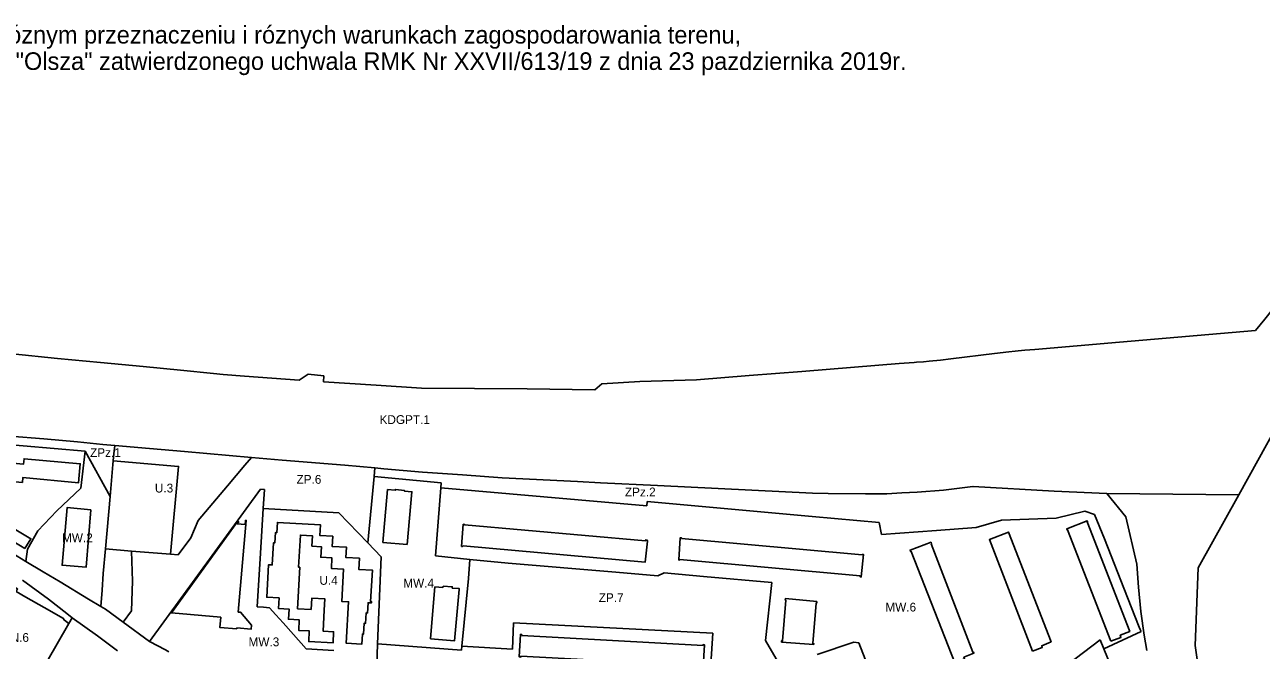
# Model space of a CAD drawing. Extents: x 7425067 to 7426806, y 5549054 to 5550619.
# Drawn here: x 7425657 to 7426359, y 5550263 to 5550619 of the extents above; entities that cross this region are included whole.
import ezdxf

# ---------------------------------------------------------------- set-up
doc = ezdxf.new("R2010")
doc.units = 0
for name, color, linetype in [('__LEGENDA_RAMKA_LOGO_PODZIAŁKA', 7, 'Continuous'), ('LIN_Linia Zabudowy Nieprzekraczalna', 7, 'Continuous'), ('LIN_linia zabudowy obowiązująca', 7, 'Continuous'), ('LIN_linie_rozgraniczajace', 7, 'Continuous'), ('TXT_Oznaczenia_przeznaczen', 7, 'Continuous')]:
    doc.layers.add(name, color=color, linetype=linetype)

msp = doc.modelspace()

# ---------------------------------------------------------------- linework, layer by layer
at = {"layer": 'LIN_Linia Zabudowy Nieprzekraczalna'}
for points in [[(7425702.5347, 5550320.8967), (7425717.29, 5550319.7), (7425739.452, 5550317.9026), (7425744.0849, 5550367.7743), (7425707.0308, 5550370.9961)], [(7425678.5251, 5550280.9263), (7425678.8, 5550281.4), (7425667.67, 5550287.68), (7425657.41, 5550293.57), (7425651.81, 5550296.72), (7425652.68, 5550298.21), (7425647.29, 5550301.26), (7425641.86, 5550304.43), (7425636.35, 5550307.4)], [(7425681.8566, 5550278.5552), (7425678.5251, 5550280.9263)]]:
    msp.add_lwpolyline(points, dxfattribs=at)
at = {"layer": 'LIN_linia zabudowy obowiązująca'}
for points in [[(7425577.83, 5550376.56), (7425576.82, 5550365.9), (7425655.37, 5550358.71), (7425655.64, 5550361.43), (7425687.2, 5550358.45), (7425688.22, 5550369.3), (7425656.31, 5550372.18), (7425656.06, 5550369.17), (7425577.83, 5550376.56)], [(7425862.71, 5550354.63), (7425860.14, 5550324.59), (7425873.91, 5550323.47), (7425876.62, 5550353.37), (7425872.39, 5550353.8), (7425872.4, 5550354.21), (7425867.21, 5550354.76), (7425867.12, 5550354.26), (7425862.71, 5550354.63)], [(7425656.83, 5550321.15), (7425660.19, 5550326.68), (7425619.2737, 5550351.0673), (7425618.47, 5550349.66), (7425616.02, 5550345.37), (7425654.29, 5550322.64), (7425656.83, 5550321.15)], [(7425694.27, 5550343.19), (7425680.89, 5550344.47), (7425677.95, 5550311.63), (7425691.61, 5550310.52), (7425694.27, 5550343.19)], [(7425777.2, 5550275.41), (7425777.27, 5550276.02), (7425785.37, 5550275.36), (7425785.53, 5550277.51), (7425779.34, 5550284.9), (7425777.95, 5550285), (7425782.51, 5550337.08), (7425782.03, 5550337.12), (7425781.82, 5550334.74), (7425777.44, 5550335.15), (7425778.26, 5550336.28), (7425777.83, 5550336.59), (7425740.04, 5550284.52), (7425768.01, 5550282.08), (7425767.5, 5550276.24), (7425777.2, 5550275.41)], [(7425826.83, 5550286.08), (7425827.18, 5550292.48), (7425819.7, 5550292.89), (7425819.35, 5550286.49), (7425811.65, 5550286.92), (7425812.95, 5550310.47), (7425812.28, 5550310.51), (7425813.28, 5550328.73), (7425820.15, 5550328.35), (7425819.83, 5550322.48), (7425825.18, 5550322.18), (7425824.85, 5550316.15), (7425831.2, 5550315.8), (7425830.87, 5550309.8), (7425837.73, 5550309.42), (7425836.72, 5550291.07), (7425840.63, 5550290.86), (7425839.33, 5550267.26), (7425848.22, 5550266.77), (7425848.54, 5550272.53), (7425849.12, 5550272.5), (7425849.46, 5550278.64), (7425850.29, 5550278.59), (7425850.61, 5550284.48), (7425851.37, 5550284.43), (7425851.69, 5550290.34), (7425853.63, 5550290.23), (7425853.67, 5550290.99), (7425853.17, 5550291.01), (7425854.15, 5550308.83), (7425846.45, 5550309.26), (7425846.8, 5550315.59), (7425839.17, 5550316.01), (7425839.49, 5550321.86), (7425831.31, 5550322.31), (7425831.63, 5550328.15), (7425824.28, 5550328.55), (7425824.62, 5550334.63), (7425800.2, 5550335.98), (7425799.87, 5550330.12), (7425799.06, 5550330.16), (7425798.73, 5550324.29), (7425797.95, 5550324.33), (7425797.25, 5550311.79), (7425795.2, 5550311.9), (7425794.18, 5550293.46), (7425801.13, 5550293.08), (7425800.8, 5550287.05), (7425806.84, 5550286.71), (7425806.52, 5550280.93), (7425812.67, 5550280.59), (7425812.34, 5550274.58), (7425818.31, 5550274.25), (7425817.98, 5550268.2), (7425831.81, 5550267.43), (7425832.17, 5550273.85), (7425826.17, 5550274.18), (7425826.83, 5550286.08)], [(7425904.72, 5550322.36), (7425905.38, 5550322.34), (7425905.66, 5550322.59), (7426009.1, 5550313.42), (7426010.32, 5550325.3), (7426010.31, 5550325.88), (7426009.39, 5550325.98), (7426009.28, 5550325.53), (7425906.56, 5550334.54), (7425906.58, 5550334.88), (7425905.76, 5550334.93), (7425904.72, 5550322.36)], [(7426273.65, 5550268.43), (7426279.27, 5550270.64), (7426278.89, 5550271.82), (7426284.27, 5550274.02), (7426260.15, 5550336.21), (7426260.34, 5550336.33), (7426260.17, 5550336.86), (7426248.49, 5550332.32), (7426248.76, 5550331.7), (7426249.03, 5550331.84), (7426273.65, 5550268.43)], [(7426132.32, 5550317.47), (7426029.73, 5550326.87), (7426029.71, 5550327.23), (7426029.02, 5550327.29), (7426028.13, 5550314.63), (7426028.77, 5550314.56), (7426028.86, 5550314.9), (7426131.14, 5550305.53), (7426131.16, 5550305.09), (7426131.82, 5550305.03), (7426133.16, 5550317.67), (7426132.38, 5550317.76), (7426132.32, 5550317.47)], [(7426229.02, 5550262.72), (7426234.63, 5550264.91), (7426234.28, 5550265.88), (7426239.6, 5550268.12), (7426215.52, 5550330.43), (7426204.64, 5550326.2), (7426229.02, 5550262.72)], [(7426171.46, 5550323.82), (7426171.67, 5550323.97), (7426171.45, 5550324.68), (7426159.59, 5550320.23), (7426159.73, 5550319.53), (7426160.08, 5550319.53), (7426184.94, 5550256.22), (7426190.42, 5550258.35), (7426190.1, 5550259.33), (7426195.78, 5550261.64), (7426195.55, 5550262.29), (7426195.1, 5550262.21), (7426171.46, 5550323.82)], [(7425894.28, 5550299.74), (7425894.18, 5550299.03), (7425889.69, 5550299.31), (7425889.51, 5550297.24), (7425887.23, 5550269.86), (7425900.82, 5550268.7), (7425903.44, 5550297.8), (7425903.46, 5550298.31), (7425899.5, 5550298.65), (7425899.51, 5550299.4), (7425894.28, 5550299.74)], [(7426106.64, 5550291.1), (7426088.78, 5550292.69), (7426088.68, 5550291.81), (7426088.9, 5550291.79), (7426087.1, 5550268.65), (7426086.59, 5550268.69), (7426086.5412, 5550268.0676), (7426086.53, 5550267.96), (7426104.84, 5550266.53)], [(7426104.84, 5550266.53), (7426104.88, 5550267.04), (7426104.38, 5550267.08), (7426106.17, 5550290.11), (7426106.54, 5550290.12), (7426106.64, 5550291.1)], [(7425938.98, 5550271.63), (7425939.01, 5550272.24), (7425938.25, 5550272.28), (7425937.56, 5550259.5), (7425938.5, 5550259.45), (7425938.53, 5550259.97), (7426041.36, 5550254.4), (7426041.33, 5550253.87), (7426042.05, 5550253.83), (7426042.74, 5550266.45), (7426042.01, 5550266.48), (7426041.99, 5550266.06), (7425938.98, 5550271.63)]]:
    msp.add_lwpolyline(points, dxfattribs=at)
at = {"layer": 'LIN_linie_rozgraniczajace'}
for points in [[(7426355.75, 5550445.02), (7426360.9629, 5550451.5429), (7426374.89, 5550468.97)], [(7426278.55, 5550438.44), (7426355.75, 5550445.02)], [(7426230.47, 5550434.34), (7426278.55, 5550438.44)], [(7425649.85, 5550431.9), (7425675.4, 5550429.25)], [(7426182.62, 5550428.95), (7426207.48, 5550431.97)], [(7426207.48, 5550431.97), (7426215.63, 5550432.92)], [(7426215.63, 5550432.92), (7426219.29, 5550433.33)], [(7426219.29, 5550433.33), (7426221.01, 5550433.53)], [(7426221.01, 5550433.53), (7426224.67, 5550433.84)], [(7426224.67, 5550433.84), (7426230.47, 5550434.34)], [(7425675.4, 5550429.25), (7425699.7, 5550426.93)], [(7425699.7, 5550426.93), (7425724, 5550424.61)], [(7425724, 5550424.61), (7425745.24, 5550422.51)], [(7426098.06, 5550421.86), (7426127.97, 5550424.23)], [(7426127.97, 5550424.23), (7426153.38, 5550426.25)], [(7426153.38, 5550426.25), (7426161.86, 5550426.92)], [(7426161.86, 5550426.92), (7426163.12, 5550427.06)], [(7426163.12, 5550427.06), (7426167.22, 5550427.33)], [(7426167.22, 5550427.33), (7426170.44, 5550427.64)], [(7426170.44, 5550427.64), (7426176.82, 5550428.25)], [(7426176.82, 5550428.25), (7426182.62, 5550428.95)], [(7425745.24, 5550422.51), (7425763.97, 5550420.64)], [(7425763.97, 5550420.64), (7425769.45, 5550420.11)], [(7425769.45, 5550420.11), (7425781.57, 5550419.07)], [(7425781.57, 5550419.07), (7425781.6228, 5550419.1447)], [(7425781.6228, 5550419.1447), (7425812.67, 5550416.89)], [(7425812.67, 5550416.89), (7425817.67, 5550420.19)], [(7425817.67, 5550420.19), (7425826.63, 5550419.37)], [(7425826.63, 5550419.37), (7425826.31, 5550415.89)], [(7426006.05, 5550416), (7426038.26, 5550417.11)], [(7426038.26, 5550417.11), (7426068.15, 5550419.49)], [(7426068.15, 5550419.49), (7426098.06, 5550421.86)], [(7425826.31, 5550415.89), (7425856.24, 5550413.95)], [(7425856.24, 5550413.95), (7425882.11, 5550412.28)], [(7425882.11, 5550412.28), (7425912.11, 5550412.09)], [(7425912.11, 5550412.09), (7425942.1, 5550411.9)], [(7425942.1, 5550411.9), (7425980.47, 5550411.4)], [(7425980.47, 5550411.4), (7425984.56, 5550414.68)], [(7425984.56, 5550414.68), (7426006.05, 5550416)], [(7426372.85, 5550399.52), (7426346.2738, 5550351.7074), (7426323.13, 5550310.07)], [(7425585.24, 5550385.53), (7425691.07, 5550376.4)], [(7425648.39, 5550385.1), (7425667.565, 5550383.43)], [(7425667.565, 5550383.43), (7425686.74, 5550381.76)], [(7425686.74, 5550381.76), (7425701.09, 5550380.3)], [(7425688.6, 5550355.51), (7425691.07, 5550376.4)], [(7425691.07, 5550376.4), (7425705.23, 5550350.79)], [(7425701.09, 5550380.3), (7425707.8196, 5550379.72)], [(7425706.84, 5550368.855), (7425707.0323, 5550370.996), (7425707.39, 5550374.98)], [(7425707.39, 5550374.98), (7425707.8196, 5550379.72)], [(7425707.8196, 5550379.72), (7425727.615, 5550377.985)], [(7425727.615, 5550377.985), (7425747.41, 5550376.25)], [(7425747.41, 5550376.25), (7425785.51, 5550372.9)], [(7425705.23, 5550350.79), (7425706.84, 5550368.855)], [(7425781.8, 5550368.51), (7425771.85, 5550356.7)], [(7425785.51, 5550372.9), (7425781.8, 5550368.51)], [(7425785.51, 5550372.9), (7425802.92, 5550371.41)], [(7425802.92, 5550371.41), (7425838.54, 5550368.48)], [(7425838.54, 5550368.48), (7425855.5928, 5550366.9389), (7425860.615, 5550366.485)], [(7425851.5702, 5550324.3387), (7425855.127, 5550361.9997)], [(7425855.127, 5550361.9997), (7425855.5928, 5550366.9389)], [(7425855.127, 5550361.9997), (7425893.26, 5550358.43)], [(7425860.615, 5550366.485), (7425882.69, 5550364.49)], [(7425882.69, 5550364.49), (7425905.32, 5550362.95)], [(7425905.32, 5550362.95), (7425927.95, 5550361.41)], [(7425927.95, 5550361.41), (7425970.63, 5550359.24)], [(7425675.02, 5550342.55), (7425688.6, 5550355.51)], [(7425727.5, 5550268.18), (7425790.71, 5550354.97)], [(7425771.85, 5550356.7), (7425755.28, 5550337.04)], [(7425790.71, 5550354.97), (7425792.82, 5550354.77)], [(7425792.82, 5550354.77), (7425792.11, 5550343.91)], [(7425889.9668, 5550316.9493), (7425893.0369, 5550355.6195)], [(7425893.26, 5550358.43), (7425893.0369, 5550355.6195)], [(7425893.0369, 5550355.6195), (7426009.9803, 5550345.3572)], [(7425970.63, 5550359.24), (7425983.7, 5550358.535)], [(7425983.7, 5550358.535), (7426016.01, 5550356.965)], [(7426016.01, 5550356.965), (7426104.07, 5550352.52)], [(7426163.5, 5550353.14), (7426178.47, 5550354.32)], [(7426178.47, 5550354.32), (7426195.1, 5550356.31)], [(7426195.1, 5550356.31), (7426195.4, 5550356.37)], [(7426195.4, 5550356.37), (7426241.4, 5550353.76)], [(7426241.4, 5550353.76), (7426271.37, 5550352.37)], [(7425701.27, 5550306.87), (7425702.5347, 5550320.8967), (7425705.23, 5550350.79)], [(7426009.9803, 5550345.3572), (7426010.1848, 5550347.8353)], [(7426010.1848, 5550347.8353), (7426103.94, 5550339.34)], [(7426104.07, 5550352.52), (7426113.095, 5550352.33)], [(7426113.095, 5550352.33), (7426134.24, 5550352.215)], [(7426134.24, 5550352.215), (7426146.36, 5550352.29)], [(7426146.36, 5550352.29), (7426154.93, 5550352.715)], [(7426154.93, 5550352.715), (7426163.5, 5550353.14)], [(7426271.37, 5550352.37), (7426346.2738, 5550351.7074)], [(7426271.37, 5550352.37), (7426282.16, 5550339.09)], [(7425664.19, 5550331.18), (7425675.02, 5550342.55)], [(7425790.56, 5550318.535), (7425792.11, 5550343.91)], [(7425792.11, 5550343.91), (7425835.13, 5550341.51)], [(7425835.13, 5550341.51), (7425851.5702, 5550324.3387)], [(7426103.94, 5550339.34), (7426142.0181, 5550335.8897)], [(7426242.565, 5550338.4725), (7426258.834, 5550342.4247)], [(7426258.834, 5550342.4247), (7426264.3505, 5550340.5538)], [(7426264.3505, 5550340.5538), (7426269.867, 5550326.6156)], [(7425657.37, 5550313.83), (7425620.3342, 5550336.5629)], [(7425755.28, 5550337.04), (7425751.07, 5550327.29)], [(7426142.0181, 5550335.8897), (7426143.2444, 5550329.1413)], [(7426174.4969, 5550331.4332), (7426197.143, 5550333.0939)], [(7426197.143, 5550333.0939), (7426211.4762, 5550337.3265)], [(7426211.4762, 5550337.3265), (7426242.565, 5550338.4725)], [(7426288.27, 5550312.19), (7426282.16, 5550339.09)], [(7425658.22, 5550320.76), (7425664.19, 5550331.18)], [(7425751.07, 5550327.29), (7425743.8, 5550317.55)], [(7426143.2444, 5550329.1413), (7426174.4969, 5550331.4332)], [(7426269.867, 5550326.6156), (7426283.0738, 5550293.2466)], [(7425657.37, 5550313.83), (7425658.22, 5550320.76)], [(7425743.8, 5550317.55), (7425739.452, 5550317.9026), (7425717.29, 5550319.7)], [(7425717.29, 5550319.7), (7425717.95, 5550302.48)], [(7425788.7, 5550288.04), (7425790.56, 5550318.535)], [(7425851.5702, 5550324.3387), (7425859.19, 5550316.38)], [(7425667.1, 5550307.97), (7425657.37, 5550313.83)], [(7425859.19, 5550316.38), (7425857.1227, 5550267.0118)], [(7425909.42, 5550314.84), (7425889.9668, 5550316.9493)], [(7425908.72, 5550304.1), (7425909.42, 5550314.84)], [(7425909.42, 5550314.84), (7425931.2507, 5550312.8515)], [(7425931.2507, 5550312.8515), (7425992.4494, 5550307.662)], [(7426289.26, 5550299.23), (7426288.27, 5550312.19)], [(7425676.83, 5550302.11), (7425667.1, 5550307.97)], [(7425700.77, 5550297.37), (7425701.27, 5550306.87)], [(7425905.05, 5550265.63), (7425908.72, 5550304.1)], [(7425992.4494, 5550307.662), (7426016.1984, 5550305.6976)], [(7426016.1984, 5550305.6976), (7426019.785, 5550307.36)], [(7426019.785, 5550307.36), (7426042.285, 5550305.2299)], [(7426042.285, 5550305.2299), (7426081.0282, 5550301.7353)], [(7426323.13, 5550310.07), (7426321.38, 5550266.04)], [(7425655.49, 5550303.07), (7425660.44, 5550299.57)], [(7425660.44, 5550299.57), (7425670.2, 5550292.33)], [(7425692.94, 5550292.37), (7425676.83, 5550302.11)], [(7425700, 5550288.15), (7425700.77, 5550297.37)], [(7425717.95, 5550302.48), (7425717.33, 5550285.72)], [(7426081.0282, 5550301.7353), (7426077.38, 5550268.79)], [(7426290.62, 5550285.42), (7426289.26, 5550299.23)], [(7425670.2, 5550292.33), (7425680.65, 5550284.24)], [(7425700, 5550288.15), (7425692.94, 5550292.37)], [(7426283.0738, 5550293.2466), (7426289.7093, 5550276.4812)], [(7425680.65, 5550284.24), (7425683.71, 5550281.8)], [(7425702.51, 5550286.65), (7425700, 5550288.15)], [(7425712.54, 5550279.24), (7425702.51, 5550286.65)], [(7425717.33, 5550285.72), (7425712.54, 5550279.24)], [(7425792.24, 5550287.705), (7425788.7, 5550288.04)], [(7425795.78, 5550287.37), (7425792.24, 5550287.705)], [(7425799.385, 5550283.445), (7425795.78, 5550287.37)], [(7425803.51, 5550278.96), (7425799.385, 5550283.445)], [(7426292.49, 5550271.86), (7426290.62, 5550285.42)], [(7425669.35, 5550256.66), (7425681.8566, 5550278.5552), (7425683.71, 5550281.8)], [(7425683.71, 5550281.8), (7425698.09, 5550271.56)], [(7425727.5, 5550268.18), (7425712.54, 5550279.24)], [(7425813.68, 5550267.38), (7425803.51, 5550278.96)], [(7425934.2804, 5550278.7998), (7425933.7, 5550263.93)], [(7426047.44, 5550273.06), (7425934.2804, 5550278.7998)], [(7426289.7093, 5550276.4812), (7426290.22, 5550275.1907)], [(7425698.09, 5550271.56), (7425709.34, 5550263.01)], [(7426044.9249, 5550231.9677), (7426047.44, 5550273.06)], [(7426234.43, 5550243.93), (7426267.52, 5550269.19)], [(7426267.52, 5550269.19), (7426269.5871, 5550264.0774)], [(7426290.7307, 5550273.9003), (7426269.5871, 5550264.0774)], [(7426290.22, 5550275.1907), (7426290.7307, 5550273.9003)], [(7426293.97, 5550263.21), (7426292.49, 5550271.86)], [(7425736.62, 5550263.51), (7425727.5, 5550268.18)], [(7425738.59, 5550262.44), (7425736.62, 5550263.51)], [(7425816.57, 5550264.13), (7425813.68, 5550267.38)], [(7425832.32, 5550263.1), (7425816.57, 5550264.13)], [(7425857.1227, 5550267.0118), (7425856.64, 5550254.66)], [(7425904.76, 5550263.34), (7425857.1227, 5550267.0118)], [(7425905.05, 5550265.63), (7425904.76, 5550263.34)], [(7425933.7, 5550263.93), (7425905.05, 5550265.63)], [(7426077.38, 5550268.79), (7426086.09, 5550253.9)], [(7426106.855, 5550260.87), (7426127.62, 5550267.84)], [(7426127.62, 5550267.84), (7426130.4554, 5550267.4389)], [(7426130.4554, 5550267.4389), (7426161.5, 5550187.3)], [(7426269.5871, 5550264.0774), (7426273.33, 5550254.79)], [(7426321.38, 5550266.04), (7426325.98, 5550234.23)]]:
    msp.add_lwpolyline(points, dxfattribs=at)

# ---------------------------------------------------------------- texts
at = {"layer": '__LEGENDA_RAMKA_LOGO_PODZIAŁKA'}
for s, p in [('Material pomocniczy zawierajacy linie rozgraniczajace teren o róznym przeznaczeniu i róznych warunkach zagospodarowania terenu, ', (7425273.469, 5550608.2172)), ('opracowane w skali 1:1000 pochodzace z Miejscowego Planu Zagospodarowania Przestrzennego "Olsza" zatwierdzonego uchwala RMK Nr XXVII/613/19 z dnia 23 pazdziernika 2019r.', (7425066.5281, 5550593.2172))]:
    msp.add_text(s, height=10, dxfattribs=at).set_placement(p)
at = {"layer": 'TXT_Oznaczenia_przeznaczen'}
for s, p in [('KDGPT.1', (7425858.2309, 5550391.9262)), ('ZPz.1', (7425693.8319, 5550373.1579)), ('ZP.6', (7425811.0782, 5550357.951)), ('U.3', (7425730.6307, 5550352.9945)), ('ZPz.2', (7425997.5798, 5550350.7726)), ('MW.2', (7425677.9076, 5550324.7334)), ('U.4', (7425824.0866, 5550300.5223)), ('MW.4', (7425871.7187, 5550298.959)), ('ZP.7', (7425982.7221, 5550290.702)), ('MW.6', (7426145.5127, 5550285.3198)), ('MN.6', (7425643.145, 5550268.0835)), ('MW.3', (7425783.8284, 5550265.5842))]:
    msp.add_text(s, height=5, dxfattribs=at).set_placement(p)

doc.saveas('drawing.dxf')
